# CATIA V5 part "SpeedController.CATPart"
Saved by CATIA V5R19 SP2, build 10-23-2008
Part number: SpeedController
Revision: ANY
Definition: UNKNOWN
Nomenclature: SpeedController
Source: Unknown
Bounding box of the stored display mesh (mm): x -14 to 14, y 0 to 8, z -13.977 to 13.977
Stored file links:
  Z:\fausse table rondelle-20220905T211342Z-001\fausse table rondelle\SpeedController.CATPart
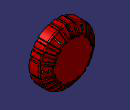
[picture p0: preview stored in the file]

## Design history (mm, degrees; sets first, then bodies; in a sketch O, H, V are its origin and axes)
AxisSystem1: origin (0, 0, 0), X (1, 0, 0), Y (0, 1, 0), Z (0, 0, 1)
Body1 "Schnitt-Linear austragen3" (main body)
  Solid1: solid without history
